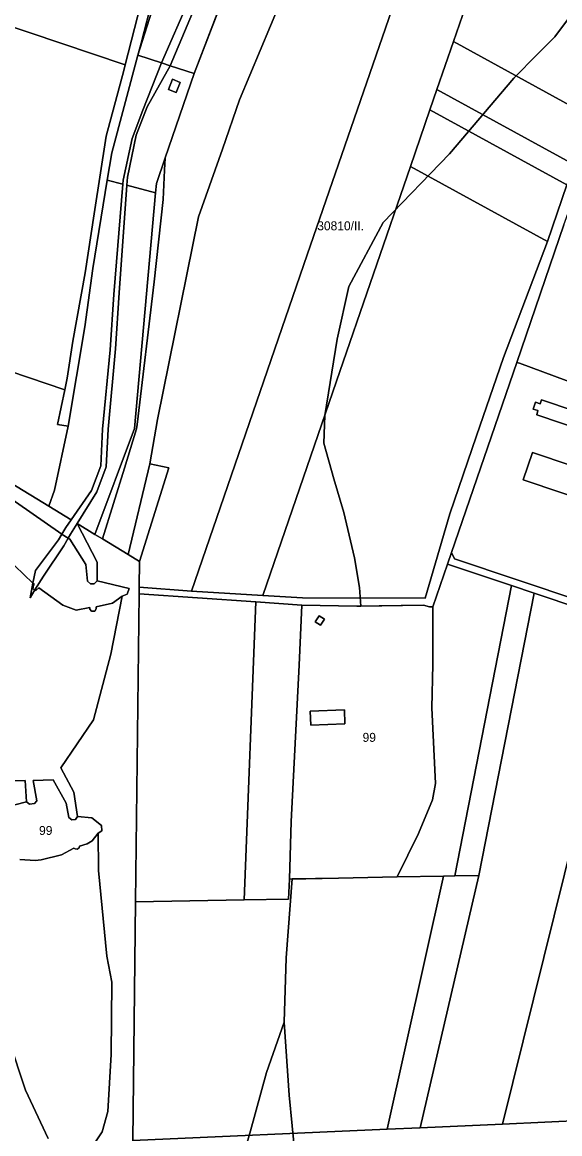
# Model space of a CAD drawing. Extents: x -545779 to -541342, y -1153413 to -1149956.
# Drawn here: x -544366 to -544067, y -1152262 to -1151643 of the extents above; entities that cross this region are included whole.
import ezdxf

# ---------------------------------------------------------------- set-up
doc = ezdxf.new("R2010")
doc.units = 0
for name, color, linetype in [('95560013', 7, 'Continuous'), ('95590013', 7, 'Continuous'), ('95610013', 7, 'Continuous'), ('95630013', 7, 'Continuous'), ('95640013', 7, 'Continuous'), ('95660013', 7, 'Continuous')]:
    doc.layers.add(name, color=color, linetype=linetype)

msp = doc.modelspace()

# ---------------------------------------------------------------- linework, layer by layer
at = {"layer": '95560013'}
for points in [[(-544411.63, -1151619.63), (-544385.88, -1151566.12), (-544374.27, -1151550.18), (-544348.98, -1151514.49), (-544275.88, -1151539.22), (-544308.61, -1151666.67), (-544415.57, -1151630.49)], [(-544284.33, -1151891.06), (-544294.92, -1151888.75), (-544290.68, -1151864.11), (-544267.74, -1151751.17), (-544254.45, -1151713.57), (-544245, -1151686.13), (-544221.98, -1151631.1), (-544212.31, -1151607.99), (-544210.19, -1151603.35), (-544198.06, -1151577.18), (-544192.36, -1151565.06), (-544182.04, -1151569.98), (-544158.48, -1151580.44), (-544142.74, -1151585.3), (-544207.19, -1151772.47), (-544271.64, -1151959.64), (-544300.75, -1151957.52), (-544300.59, -1151943.25)], [(-544190.89, -1151842.68), (-544232.03, -1151962.15), (-544271.64, -1151959.64), (-544207.19, -1151772.47), (-544142.74, -1151585.3), (-544139.74, -1151586.23), (-544118.3, -1151593.88), (-544107.46, -1151600.39), (-544125.78, -1151653.59), (-544135.01, -1151680.4), (-544138.91, -1151691.71), (-544149.76, -1151723.23)], [(-544060.91, -1151627.39), (-544042.66, -1151635.02), (-544031.62, -1151641.99), (-544049.74, -1151695.3), (-544125.78, -1151653.59), (-544107.46, -1151600.39), (-544080.04, -1151616.83)], [(-544319.09, -1151706.41), (-544325.87, -1151749.51), (-544330.86, -1151782.36), (-544337.64, -1151820.46), (-544340.91, -1151841.16), (-544342.22, -1151847.52), (-544474.71, -1151802.71), (-544442.81, -1151708.38), (-544438.68, -1151702.96), (-544432.02, -1151684.69), (-544431.97, -1151675.83), (-544415.57, -1151630.49), (-544308.61, -1151666.67), (-544309.29, -1151669.8)], [(-544090.59, -1151832.3), (-544064.41, -1151755.76), (-544046.26, -1151705.45), (-544027.3, -1151651.05), (-544026.21, -1151647.92), (-544025.31, -1151648.91), (-544023.42, -1151650.98), (-544000.97, -1151670.79), (-543983.48, -1151684.21), (-543964.31, -1151698.48), (-544019.06, -1151858.7), (-544089.09, -1151832.83)], [(-544049.74, -1151695.3), (-544058.9, -1151722.15), (-544135.01, -1151680.4), (-544125.78, -1151653.59)], [(-544062.77, -1151733.47), (-544138.91, -1151691.71), (-544135.01, -1151680.4), (-544058.9, -1151722.15)], [(-544149.76, -1151723.23), (-544138.91, -1151691.71), (-544062.77, -1151733.47), (-544073.55, -1151765.03)], [(-544101.95, -1151840.94), (-544113, -1151873.27), (-544127.82, -1151916.61), (-544141.65, -1151963.58), (-544209.95, -1151963.48), (-544232.03, -1151962.15), (-544190.89, -1151842.68), (-544149.76, -1151723.23), (-544073.55, -1151765.03), (-544098.06, -1151829.56)], [(-544346.23, -1151866.95), (-544340.28, -1151867.89), (-544347.9, -1151903.54), (-544351.13, -1151912.42), (-544407.5, -1151878.02), (-544496.26, -1151864.52), (-544483.08, -1151827.46), (-544474.71, -1151802.71), (-544342.22, -1151847.52)], [(-544157.13, -1152118.8), (-544145.23, -1152094.69), (-544137.48, -1152075.92), (-544135.77, -1152066.84), (-544137.89, -1152024.68), (-544137.24, -1152000.5), (-544137.3, -1151975.86), (-544137.32, -1151968.36), (-544129.21, -1151944.71), (-544093.57, -1151956.63), (-544125.14, -1152118.25), (-544131.46, -1152118.36)], [(-544111.7, -1152118.02), (-544125.14, -1152118.25), (-544093.57, -1151956.63), (-544080.99, -1151960.83)], [(-544300.79, -1151961.28), (-544235.82, -1151965.72), (-544242.36, -1152131.69), (-544302.75, -1152132.72)], [(-544080.99, -1151960.83), (-544029.6, -1151978.02), (-544064.04, -1152117.23), (-544098.47, -1152256.44), (-544144.44, -1152258.48), (-544111.7, -1152118.02)], [(-544235.82, -1151965.72), (-544210.18, -1151967.43), (-544211.7, -1152001), (-544216.21, -1152087.96), (-544217.12, -1152120.01), (-544217.65, -1152131.29), (-544242.36, -1152131.69)], [(-544064.04, -1152117.23), (-544029.6, -1151978.02), (-543979.89, -1151994.64), (-544015.64, -1152124.55), (-544051.35, -1152254.35), (-544098.47, -1152256.44)], [(-544189.83, -1152119.54), (-544157.13, -1152118.8), (-544131.46, -1152118.36), (-544162.8, -1152259.29), (-544304.26, -1152265.56), (-544302.75, -1152132.72), (-544242.36, -1152131.69), (-544217.65, -1152131.29), (-544217.12, -1152120.01)], [(-544125.14, -1152118.25), (-544111.7, -1152118.02), (-544144.44, -1152258.48), (-544162.8, -1152259.29), (-544131.46, -1152118.36)]]:
    msp.add_lwpolyline(points, close=True, dxfattribs=at)
at = {"layer": '95590013'}
for points in [[(-544283.6, -1151667.09), (-544247.16, -1151580.61), (-544236.52, -1151584.18), (-544270.24, -1151671.42)], [(-544256.81, -1151593.28), (-544288.37, -1151665.55), (-544301.51, -1151661.3), (-544299.76, -1151654.55), (-544286.65, -1151603.93), (-544272.13, -1151607.7), (-544265.97, -1151589.28)]]:
    msp.add_lwpolyline(points, close=True, dxfattribs=at)
at = {"layer": '95610013'}
for points in [[(-544221.23, -1151545.74), (-544214.8, -1151550.04), (-544215.31, -1151551.2), (-544245, -1151619.57), (-544221.98, -1151631.1), (-544245, -1151686.13), (-544254.45, -1151713.57), (-544267.74, -1151751.17), (-544290.68, -1151864.11), (-544294.92, -1151888.75), (-544306.99, -1151939.34), (-544321.27, -1151930.63), (-544309.03, -1151891.14), (-544302.25, -1151869.25), (-544301.96, -1151866.85), (-544292.37, -1151787.39), (-544287.51, -1151741.53), (-544286.67, -1151725.2), (-544286.32, -1151718.42), (-544270.24, -1151671.42), (-544236.52, -1151584.18), (-544221.72, -1151546.98)], [(-544294.92, -1151888.75), (-544284.33, -1151891.06), (-544300.59, -1151943.25), (-544306.99, -1151939.34)]]:
    msp.add_lwpolyline(points, close=True, dxfattribs=at)
at = {"layer": '95630013'}
for points in [[(-544247.16, -1151580.61), (-544283.6, -1151667.09), (-544296.39, -1151690.01), (-544302.4, -1151705.73), (-544307.28, -1151729.26), (-544307.61, -1151733.71), (-544312.02, -1151793.5), (-544313.95, -1151824.81), (-544318.14, -1151869.59), (-544319.12, -1151890.49), (-544324.34, -1151904.33), (-544335.32, -1151922.05), (-544339.01, -1151928), (-544340.3, -1151930.26), (-544343.61, -1151928.24), (-544343.86, -1151928.06), (-544341.54, -1151924.32), (-544338.6, -1151920.06), (-544327.25, -1151903.59), (-544322.08, -1151889.98), (-544321.13, -1151869.42), (-544316.9, -1151825.34), (-544314.86, -1151794.47), (-544309.95, -1151733.1), (-544309.78, -1151730.92), (-544304.78, -1151707.55), (-544298.72, -1151691.91), (-544288.37, -1151665.55), (-544256.81, -1151593.28)], [(-544380.21, -1151935.96), (-544359.92, -1151955.29), (-544361.52, -1151963.36), (-544358.82, -1151959.02), (-544358.28, -1151959.35), (-544356.59, -1151957.94), (-544343.35, -1151967.55), (-544335.79, -1151970.29), (-544328.31, -1151968.86), (-544328.27, -1151969.8), (-544327.33, -1151970.85), (-544325.56, -1151970.82), (-544324.75, -1151969.59), (-544324.77, -1151968.37), (-544315.72, -1151966.44), (-544310.19, -1151962.57), (-544316.5, -1151994.78), (-544326.24, -1152031.41), (-544344.45, -1152058.12), (-544337.16, -1152071.6), (-544335.04, -1152085.17), (-544336.29, -1152086.92), (-544338.27, -1152087.14), (-544339.92, -1152085.72), (-544341.48, -1152077.72), (-544348.76, -1152064.81), (-544359.73, -1152065.07), (-544357.72, -1152076.38), (-544359.11, -1152078.01), (-544361.86, -1152078.39), (-544363.49, -1152077.04), (-544364.32, -1152065.07), (-544372.46, -1152065.31)], [(-544367.17, -1152109.21), (-544358.62, -1152109.71), (-544355.29, -1152109.31), (-544344.05, -1152106.47), (-544337.22, -1152102.77), (-544336.39, -1152103.29), (-544335.3, -1152103.34), (-544334.24, -1152102.61), (-544334.06, -1152101.63), (-544329.79, -1152100.46), (-544326.99, -1152098.74), (-544323.67, -1152094.51), (-544323.35, -1152115.35), (-544318.85, -1152162.91), (-544316.07, -1152177.36), (-544316.37, -1152217.67), (-544318.19, -1152249.38), (-544321.33, -1152260.74), (-544329.4, -1152272.8)], [(-544351.36, -1152264.49), (-544364.14, -1152237.5), (-544382.81, -1152181.59)]]:
    msp.add_lwpolyline(points, dxfattribs=at)
for points in [[(-544329.5, -1151954.11), (-544330.43, -1151944.8), (-544339.35, -1151930.84), (-544340.3, -1151930.26), (-544339.01, -1151928), (-544335.32, -1151922.05), (-544324.12, -1151943.48), (-544324.19, -1151954.02), (-544325.78, -1151955.64), (-544327.84, -1151955.63)], [(-544359.3, -1151955.88), (-544359.64, -1151956.45), (-544359.96, -1151958.33), (-544358.82, -1151959.02), (-544361.52, -1151963.36), (-544359.92, -1151955.29)]]:
    msp.add_lwpolyline(points, close=True, dxfattribs=at)
at = {"layer": '95640013'}
for points in [[(-544286.65, -1151603.93), (-544299.76, -1151654.55), (-544301.51, -1151661.3), (-544316.07, -1151715.64), (-544318.54, -1151730.85), (-544326.52, -1151780.05), (-544331.12, -1151812.43), (-544340.28, -1151867.89), (-544346.23, -1151866.95), (-544342.22, -1151847.52), (-544340.91, -1151841.16), (-544337.64, -1151820.46), (-544330.86, -1151782.36), (-544325.87, -1151749.51), (-544319.09, -1151706.41), (-544309.29, -1151669.8), (-544308.61, -1151666.67), (-544275.88, -1151539.22)], [(-544064.41, -1151755.76), (-544090.59, -1151832.3), (-544126.97, -1151938.18), (-544129.21, -1151944.71), (-544137.32, -1151968.36), (-544139.1, -1151968.37), (-544142.54, -1151967.58), (-544179.69, -1151968.08), (-544210.18, -1151967.43), (-544235.82, -1151965.72), (-544300.79, -1151961.28), (-544300.75, -1151957.52), (-544271.64, -1151959.64), (-544232.03, -1151962.15), (-544209.95, -1151963.48), (-544141.65, -1151963.58), (-544127.82, -1151916.61), (-544113, -1151873.27), (-544101.95, -1151840.94), (-544098.06, -1151829.56), (-544073.55, -1151765.03), (-544062.77, -1151733.47)], [(-544407.5, -1151878.02), (-544351.13, -1151912.42), (-544338.6, -1151920.06), (-544341.54, -1151924.32), (-544343.86, -1151928.06), (-544377.68, -1151904.35)], [(-544329.4, -1152272.8), (-544321.33, -1152260.74), (-544318.19, -1152249.38), (-544316.37, -1152217.67), (-544316.07, -1152177.36), (-544318.85, -1152162.91), (-544323.35, -1152115.35), (-544323.67, -1152094.51), (-544321.62, -1152093.12), (-544321.84, -1152090.12), (-544327.11, -1152085.89), (-544335.04, -1152085.17), (-544337.16, -1152071.6), (-544344.45, -1152058.12), (-544326.24, -1152031.41), (-544316.5, -1151994.78), (-544310.19, -1151962.57), (-544307.44, -1151961.3), (-544306.41, -1151958.16), (-544324.19, -1151954.02), (-544324.12, -1151943.48), (-544335.32, -1151922.05), (-544325.42, -1151928.09), (-544321.27, -1151930.63), (-544306.99, -1151939.34), (-544300.59, -1151943.25), (-544300.75, -1151957.52), (-544300.79, -1151961.28), (-544302.75, -1152132.72), (-544304.26, -1152265.56)], [(-544383.11, -1152082.09), (-544363.49, -1152077.04), (-544361.86, -1152078.39), (-544359.11, -1152078.01), (-544357.72, -1152076.38), (-544359.73, -1152065.07), (-544348.76, -1152064.81), (-544341.48, -1152077.72), (-544339.92, -1152085.72), (-544338.27, -1152087.14), (-544336.29, -1152086.92), (-544335.04, -1152085.17), (-544327.11, -1152085.89), (-544321.84, -1152090.12), (-544321.62, -1152093.12), (-544323.67, -1152094.51), (-544326.99, -1152098.74), (-544329.79, -1152100.46), (-544334.06, -1152101.63), (-544334.24, -1152102.61), (-544335.3, -1152103.34), (-544336.39, -1152103.29), (-544337.22, -1152102.77), (-544344.05, -1152106.47), (-544355.29, -1152109.31), (-544358.62, -1152109.71), (-544367.17, -1152109.21)], [(-544372.46, -1152065.31), (-544364.32, -1152065.07), (-544363.49, -1152077.04), (-544383.11, -1152082.09)], [(-544382.81, -1152181.59), (-544364.14, -1152237.5), (-544351.36, -1152264.49)]]:
    msp.add_lwpolyline(points, dxfattribs=at)
for points in [[(-544304.78, -1151707.55), (-544309.78, -1151730.92), (-544309.95, -1151733.1), (-544318.54, -1151730.85), (-544316.07, -1151715.64), (-544301.51, -1151661.3), (-544288.37, -1151665.55), (-544298.72, -1151691.91)], [(-544286.32, -1151718.42), (-544291.18, -1151732.61), (-544291.65, -1151737.89), (-544307.61, -1151733.71), (-544307.28, -1151729.26), (-544302.4, -1151705.73), (-544296.39, -1151690.01), (-544283.6, -1151667.09), (-544270.24, -1151671.42)], [(-544280.24, -1151682.01), (-544284.43, -1151680.27), (-544282.16, -1151674.67), (-544277.99, -1151676.42)], [(-544284.43, -1151680.27), (-544280.24, -1151682.01), (-544277.99, -1151676.42), (-544282.16, -1151674.67)], [(-544292.37, -1151787.39), (-544301.96, -1151866.85), (-544302.25, -1151869.25), (-544309.03, -1151891.14), (-544321.27, -1151930.63), (-544325.42, -1151928.09), (-544303.33, -1151869.09), (-544291.65, -1151737.89), (-544291.18, -1151732.61), (-544286.32, -1151718.42), (-544286.67, -1151725.2), (-544287.51, -1151741.53)], [(-544340.28, -1151867.89), (-544331.12, -1151812.43), (-544326.52, -1151780.05), (-544318.54, -1151730.85), (-544309.95, -1151733.1), (-544314.86, -1151794.47), (-544316.9, -1151825.34), (-544321.13, -1151869.42), (-544322.08, -1151889.98), (-544327.25, -1151903.59), (-544338.6, -1151920.06), (-544351.13, -1151912.42), (-544347.9, -1151903.54)], [(-544291.65, -1151737.89), (-544303.33, -1151869.09), (-544325.42, -1151928.09), (-544335.32, -1151922.05), (-544324.34, -1151904.33), (-544319.12, -1151890.49), (-544318.14, -1151869.59), (-544313.95, -1151824.81), (-544312.02, -1151793.5), (-544307.61, -1151733.71)], [(-544048.79, -1151945.7), (-544055.43, -1151965.13), (-544125.19, -1151941.77), (-544126.97, -1151938.18), (-544090.59, -1151832.3), (-544089.09, -1151832.83), (-544019.06, -1151858.7), (-544023.31, -1151871.12), (-544076.82, -1151853.08), (-544077.63, -1151855.48), (-544080.26, -1151854.52), (-544081.48, -1151858.34), (-544078.85, -1151859.19), (-544079.53, -1151861.47), (-544026.17, -1151879.49), (-544033.67, -1151902.56), (-544037.83, -1151914.31)], [(-544077.63, -1151855.48), (-544076.82, -1151853.08), (-544023.31, -1151871.12), (-544026.17, -1151879.49), (-544079.53, -1151861.47), (-544078.85, -1151859.19), (-544081.48, -1151858.34), (-544080.26, -1151854.52)], [(-544087.1, -1151897.66), (-544084.41, -1151890.05), (-544081.86, -1151882.41), (-544038.79, -1151896.97), (-544039.91, -1151900.39), (-544044.05, -1151912.21)], [(-544084.41, -1151890.05), (-544087.1, -1151897.66), (-544044.05, -1151912.21), (-544039.91, -1151900.39), (-544038.79, -1151896.97), (-544081.86, -1151882.41)], [(-544377.68, -1151904.35), (-544343.86, -1151928.06), (-544345.71, -1151931.05), (-544358.52, -1151948.28), (-544359.92, -1151955.29), (-544380.21, -1151935.96), (-544381.57, -1151928.44), (-544407.88, -1151901.07), (-544408.56, -1151898.41), (-544410.34, -1151896.31), (-544411.13, -1151894.33), (-544409.31, -1151891.54)], [(-544343.61, -1151928.24), (-544340.3, -1151930.26), (-544342.72, -1151934.53), (-544354.03, -1151951.32), (-544358.82, -1151959.02), (-544359.96, -1151958.33), (-544359.64, -1151956.45), (-544359.3, -1151955.88), (-544359.92, -1151955.29), (-544358.52, -1151948.28), (-544345.71, -1151931.05), (-544343.86, -1151928.06)], [(-544339.35, -1151930.84), (-544330.43, -1151944.8), (-544329.5, -1151954.11), (-544327.84, -1151955.63), (-544325.78, -1151955.64), (-544324.19, -1151954.02), (-544306.41, -1151958.16), (-544307.44, -1151961.3), (-544310.19, -1151962.57), (-544315.72, -1151966.44), (-544324.77, -1151968.37), (-544324.75, -1151969.59), (-544325.56, -1151970.82), (-544327.33, -1151970.85), (-544328.27, -1151969.8), (-544328.31, -1151968.86), (-544335.79, -1151970.29), (-544343.35, -1151967.55), (-544356.59, -1151957.94), (-544358.28, -1151959.35), (-544358.82, -1151959.02), (-544354.03, -1151951.32), (-544342.72, -1151934.53), (-544340.3, -1151930.26)], [(-544125.19, -1151941.77), (-544055.43, -1151965.13), (-544044.66, -1151968.73), (-544030.88, -1151973.35), (-544002.09, -1151982.98), (-543971.18, -1151993.33), (-543968.05, -1151994.38), (-543955.12, -1151998.7), (-543937.55, -1152004.59), (-543934.17, -1152002.91), (-543936.43, -1152013.38), (-543938.9, -1152008.35), (-543979.89, -1151994.64), (-544029.6, -1151978.02), (-544080.99, -1151960.83), (-544093.57, -1151956.63), (-544129.21, -1151944.71), (-544126.97, -1151938.18)], [(-544137.24, -1152000.5), (-544137.89, -1152024.68), (-544135.77, -1152066.84), (-544137.48, -1152075.92), (-544145.23, -1152094.69), (-544157.13, -1152118.8), (-544189.83, -1152119.54), (-544217.12, -1152120.01), (-544216.21, -1152087.96), (-544211.7, -1152001), (-544210.18, -1151967.43), (-544179.69, -1151968.08), (-544142.54, -1151967.58), (-544139.1, -1151968.37), (-544137.32, -1151968.36), (-544137.3, -1151975.86)], [(-544202.76, -1151976.72), (-544200.51, -1151973.46), (-544197.65, -1151975.38), (-544199.95, -1151978.67)], [(-544200.51, -1151973.46), (-544202.76, -1151976.72), (-544199.95, -1151978.67), (-544197.65, -1151975.38)], [(-544205.29, -1152034.39), (-544186.33, -1152033.54), (-544186.52, -1152025.71), (-544205.64, -1152026.57)], [(-544205.64, -1152026.57), (-544186.52, -1152025.71), (-544186.33, -1152033.54), (-544205.29, -1152034.39)], [(-544162.8, -1152259.29), (-544144.44, -1152258.48), (-544098.47, -1152256.44), (-544051.35, -1152254.35), (-544020.4, -1152252.98), (-544024.42, -1152264.45), (-544029.74, -1152268.41), (-544167.08, -1152274.5), (-544304.43, -1152280.58), (-544304.26, -1152265.56)]]:
    msp.add_lwpolyline(points, close=True, dxfattribs=at)
at = {"layer": '95660013'}
for points in [[(-544304.26, -1152265.56), (-544302.75, -1152132.72), (-544300.79, -1151961.28), (-544300.75, -1151957.52), (-544300.59, -1151943.25), (-544306.99, -1151939.34), (-544321.27, -1151930.63), (-544309.03, -1151891.14), (-544302.25, -1151869.25), (-544301.96, -1151866.85), (-544292.37, -1151787.39), (-544287.51, -1151741.53), (-544286.67, -1151725.2), (-544286.32, -1151718.42), (-544270.24, -1151671.42), (-544253.066, -1151626.784)], [(-544253.066, -1151626.784), (-544270.24, -1151671.42), (-544283.6, -1151667.09), (-544288.37, -1151665.55), (-544301.51, -1151661.3), (-544292.621, -1151633.163)], [(-544051.463, -1151626.784), (-544069.327, -1151651.027), (-544079.025, -1151660.724), (-544092.294, -1151673.994), (-544128.022, -1151716.101), (-544165.024, -1151754.38), (-544184.164, -1151790.107), (-544190.544, -1151819.455), (-544197.417, -1151861.88), (-544197.967, -1151877.308), (-544192.458, -1151897.143), (-544186.947, -1151915.877), (-544180.888, -1151941.222), (-544178.132, -1151957.752), (-544177.339, -1151968.048), (-544179.69, -1151968.08), (-544210.18, -1151967.43), (-544211.7, -1152001), (-544216.21, -1152087.96), (-544217.12, -1152120.01), (-544215.697, -1152119.985), (-544218.906, -1152163.82), (-544220.007, -1152199.634), (-544229.925, -1152227.735), (-544238.741, -1152260.243), (-544245.903, -1152285.037)], [(-544213.947, -1152274.568), (-544217.252, -1152240.407), (-544220.007, -1152199.634), (-544218.906, -1152163.82), (-544215.697, -1152119.985), (-544189.83, -1152119.54), (-544157.13, -1152118.8), (-544145.23, -1152094.69), (-544137.48, -1152075.92), (-544135.77, -1152066.84), (-544137.89, -1152024.68), (-544137.24, -1152000.5), (-544137.3, -1151975.86), (-544137.32, -1151968.36), (-544139.1, -1151968.37), (-544142.54, -1151967.58), (-544177.339, -1151968.048), (-544178.132, -1151957.752), (-544180.888, -1151941.222), (-544186.947, -1151915.877), (-544192.458, -1151897.143), (-544197.967, -1151877.308), (-544197.417, -1151861.88), (-544190.544, -1151819.455), (-544184.164, -1151790.107), (-544165.024, -1151754.38), (-544128.022, -1151716.101), (-544092.294, -1151673.994), (-544079.025, -1151660.724), (-544069.327, -1151651.027), (-544051.463, -1151626.784)], [(-544292.621, -1151633.163), (-544301.51, -1151661.3), (-544316.07, -1151715.64), (-544318.54, -1151730.85), (-544326.52, -1151780.05), (-544331.12, -1151812.43), (-544340.28, -1151867.89), (-544347.9, -1151903.54), (-544351.13, -1151912.42), (-544407.5, -1151878.02)], [(-544407.5, -1151878.02), (-544351.13, -1151912.42), (-544347.9, -1151903.54), (-544340.28, -1151867.89), (-544331.12, -1151812.43), (-544326.52, -1151780.05), (-544318.54, -1151730.85), (-544316.07, -1151715.64), (-544301.51, -1151661.3), (-544288.37, -1151665.55), (-544283.6, -1151667.09), (-544270.24, -1151671.42), (-544286.32, -1151718.42), (-544286.67, -1151725.2), (-544287.51, -1151741.53), (-544292.37, -1151787.39), (-544301.96, -1151866.85), (-544302.25, -1151869.25), (-544309.03, -1151891.14), (-544321.27, -1151930.63), (-544306.99, -1151939.34), (-544300.59, -1151943.25), (-544300.75, -1151957.52), (-544300.79, -1151961.28), (-544302.75, -1152132.72), (-544304.26, -1152265.56)], [(-544245.903, -1152285.037), (-544238.741, -1152260.243), (-544229.925, -1152227.735), (-544220.007, -1152199.634), (-544217.252, -1152240.407), (-544213.947, -1152274.568)]]:
    msp.add_lwpolyline(points, dxfattribs=at)
msp.add_lwpolyline([(-544189.83, -1152119.54), (-544215.697, -1152119.985), (-544217.12, -1152120.01), (-544216.21, -1152087.96), (-544211.7, -1152001), (-544210.18, -1151967.43), (-544179.69, -1151968.08), (-544177.339, -1151968.048), (-544142.54, -1151967.58), (-544139.1, -1151968.37), (-544137.32, -1151968.36), (-544137.3, -1151975.86), (-544137.24, -1152000.5), (-544137.89, -1152024.68), (-544135.77, -1152066.84), (-544137.48, -1152075.92), (-544145.23, -1152094.69), (-544157.13, -1152118.8)], close=True, dxfattribs=at)

# ---------------------------------------------------------------- texts
for s, p in [('30810/II.', (-544201.675, -1151758.767)), ('99', (-544176.445, -1152043.637)), ('99', (-544356.515, -1152095.484))]:
    msp.add_text(s, height=5, rotation=360, dxfattribs=at).set_placement(p)

doc.saveas('drawing.dxf')
